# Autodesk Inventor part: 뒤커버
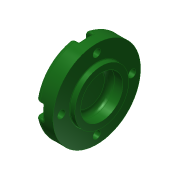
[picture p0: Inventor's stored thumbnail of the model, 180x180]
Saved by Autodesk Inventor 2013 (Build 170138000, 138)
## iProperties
Created: 2015-11
Part Number: 뒤커버
Material: 알루미늄 6061
Document SubType Name: Modeling
Designer: mduedu
Density: 1 g/cm^3
Author: mduedu
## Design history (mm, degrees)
sketch "스케치1"
  geometry: L1 (-7, 0)-(7, 0); L2 (-7, 0)-(-7, 26); L3 (-7, 26)-(4, 26); L4 (4, 26)-(4, 16); L5 (4, 16)-(7, 16); L6 (7, 16)-(7, 0); 2 further points
  constraints: 12 end point, 3 perpendicular, 2 parallel, 1 coincident, 1 horizontal, 1 midpoint
  dimensions: "d0" = 14 distance of L1.start L1.end; "d1" = 52 diameter of L3 L1; "d2" = 3 distance of L4.end L5.end; "d3" = 32 diameter of L5 L1
revolve "회전1" sketch "스케치1" stored, may be unused: angle "d4" = 90 deg
hole "구멍1" diameter "d7" = 25; stored, may be unused: countersink angle "d11" = 90 deg, drill point angle "d13" = 0 deg; dims "d8" = 6, "d9" = 4, "d10" = 2, "d12" = 8, "d62" = 10, "d63" = 10
fillet "모깎기2" dims "d36" = 3
fillet "모깎기3" dims "d37" = 3
fillet "모깎기4" dims "d38" = 0.3
sketch "스케치3" dims "d61" = 42
  geometry: C1 r 26 at (0, 0) reference; 2 further points
  constraints: 2 vertical alignment, 1 coincident, 2 other
hole "구멍4" sketch "스케치3" at (0, -21) diameter "d44" = 4.5; stored, may be unused: countersink angle "d48" = 90 deg, drill point angle "d50" = 0 deg; dims "d45" = 6, "d46" = 8, "d47" = 4.6, "d49" = 8
sketch "스케치4"
  geometry: L1 (-4, 0)-(-4, -4.69); L2 (4, 0)-(4, -4.69); A1 r 4 centre (0, 0) between (3.614, -1.714) and (-3.614, -1.714) reference; A2 r 26 centre (0, 21) between (-4, -4.69) and (4, -4.69) reference; 1 further point
  constraints: 4 end point, 4 point on circle, 2 tangent, 1 parallel, 1 vertical
extrude "돌출1" cut sketch "스케치4" stored distance "d51" = 0; taper "d52" = 0 deg
fillet "모깎기5" dims "d56" = 0.3
fillet "모깎기6" dims "d57" = 1
node "솔리드1"
pattern_circular "원형 패턴1" dims angle "d54" = 360 deg
